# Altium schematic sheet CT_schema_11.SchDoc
size 387 x 385 mm
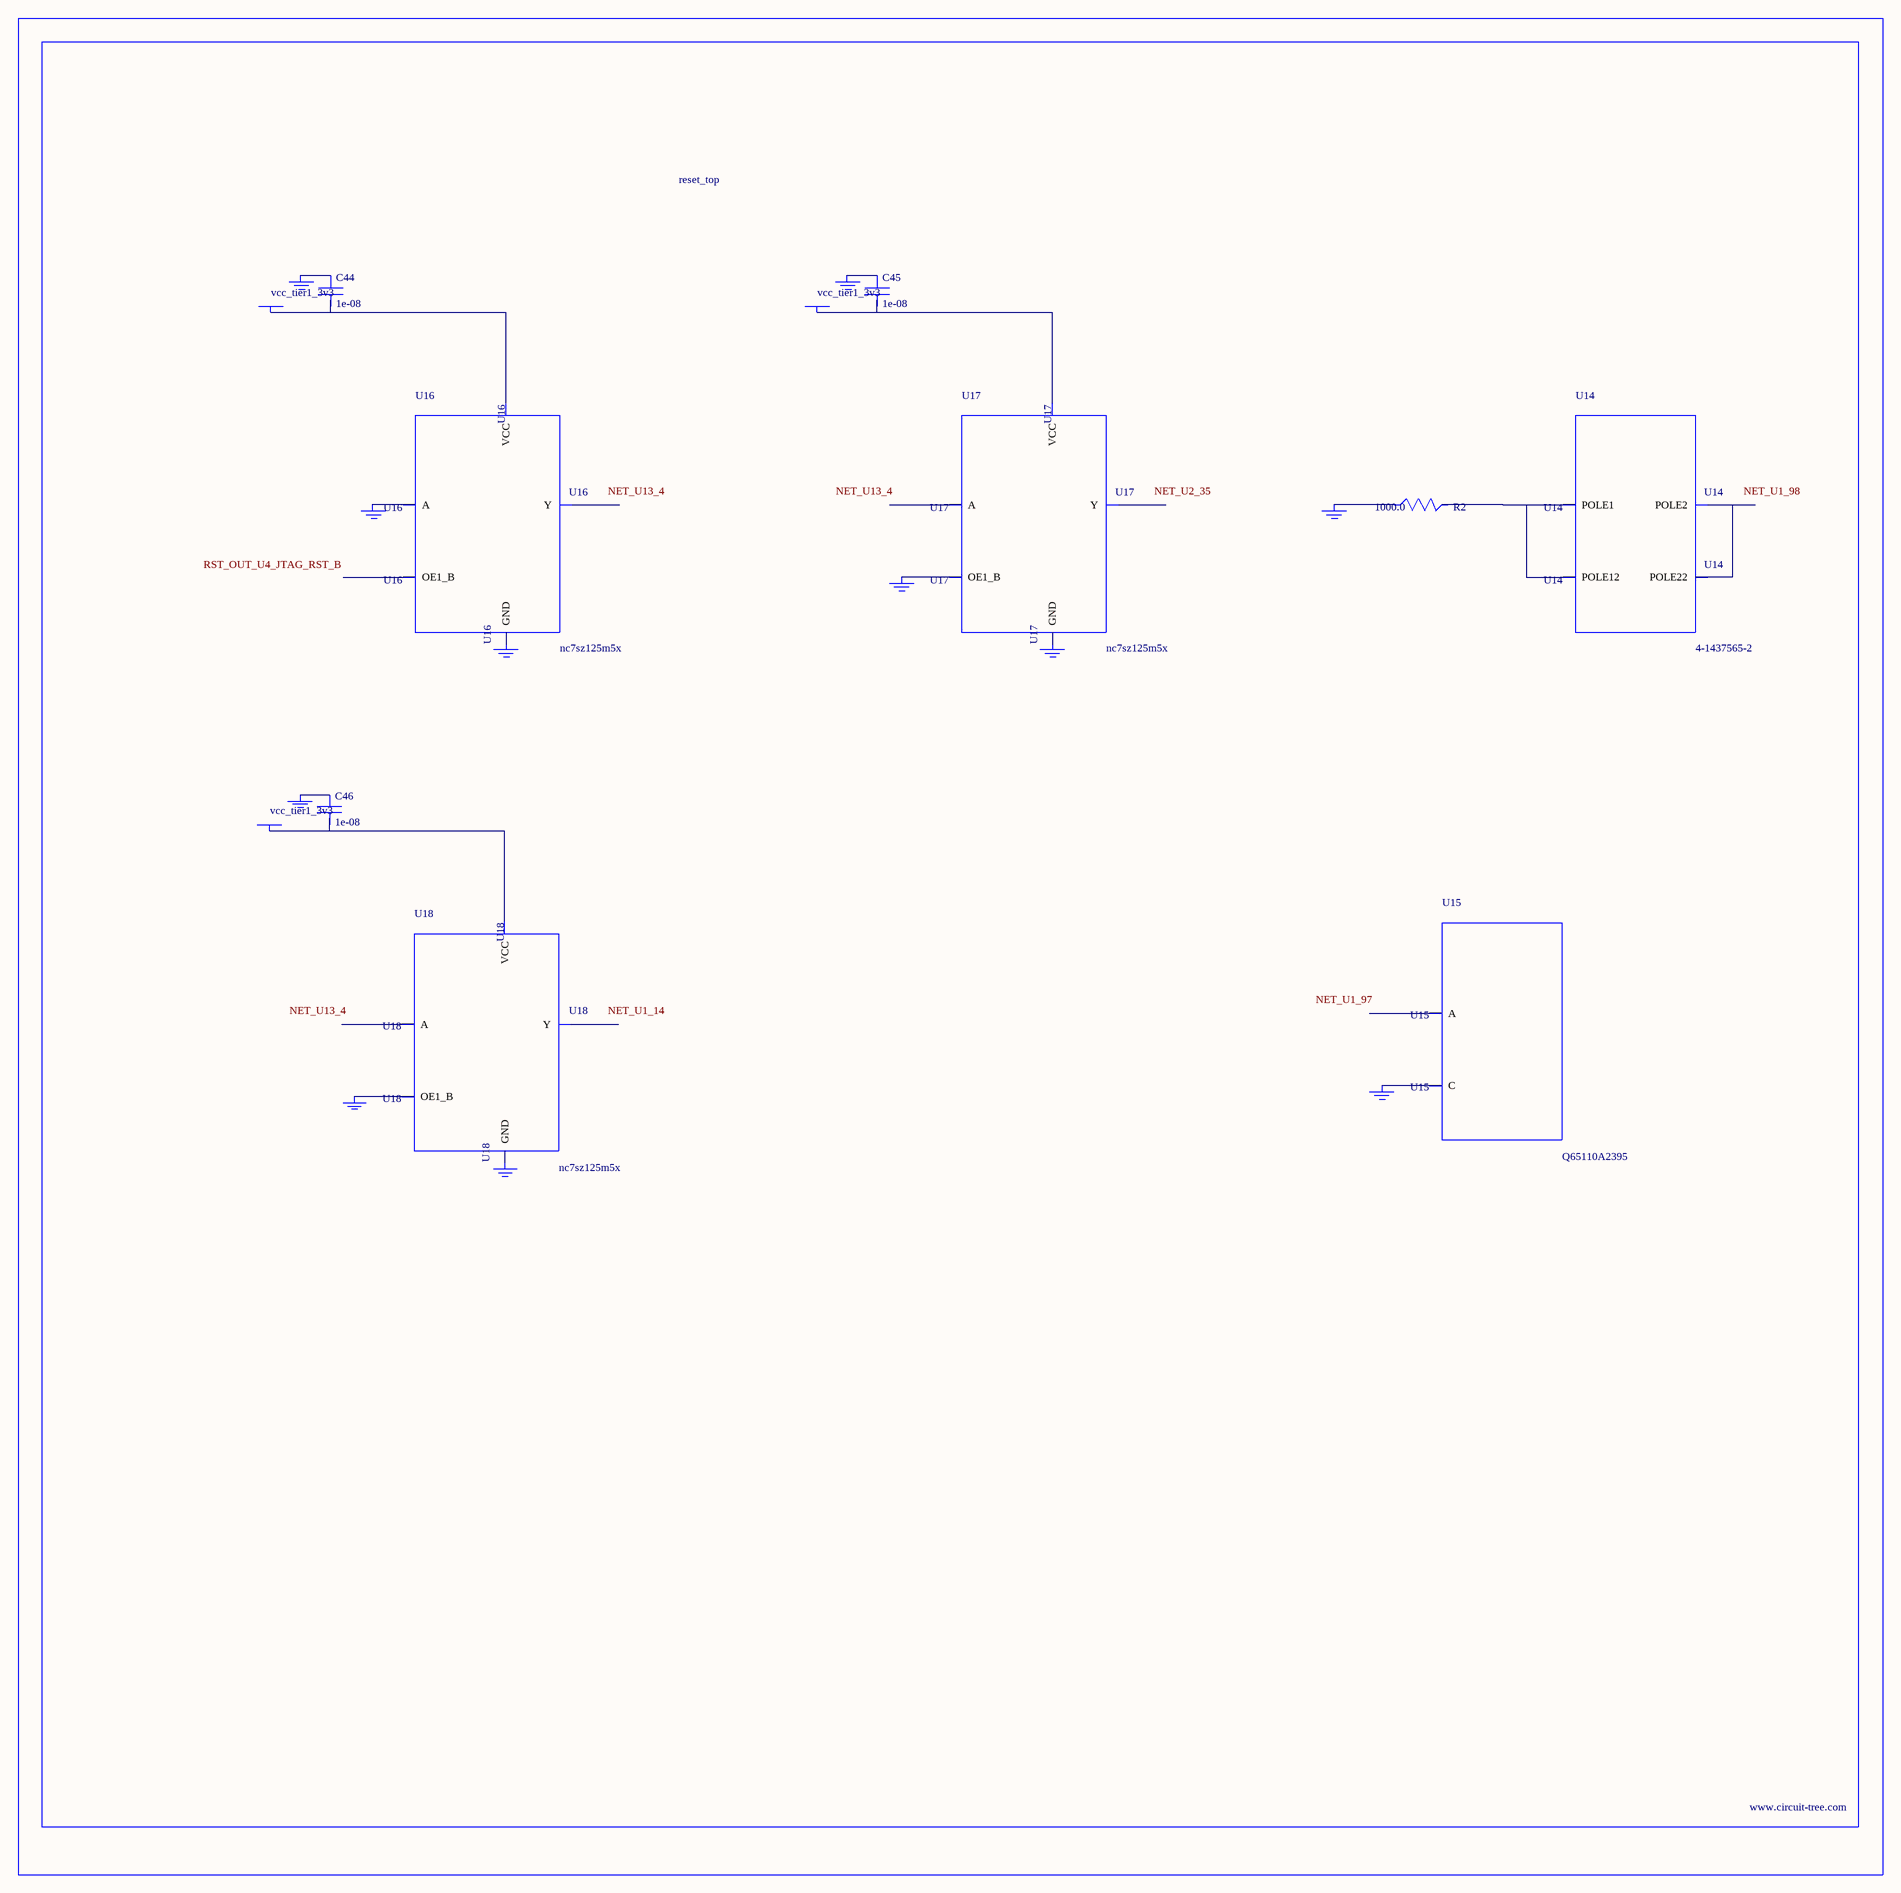
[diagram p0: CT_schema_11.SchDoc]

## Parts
BORDER10  (no value)
C44  1e-08  [C0402]
C45  1e-08  [C0402]
C46  1e-08  [C0402]
GND_INSTANCE_10_0  (no value)
GND_INSTANCE_10_1  (no value)
GND_INSTANCE_10_2  (no value)
GND_INSTANCE_10_3  (no value)
GND_INSTANCE_10_4  (no value)
GND_INSTANCE_10_5  (no value)
GND_INSTANCE_10_6  (no value)
GND_INSTANCE_10_7  (no value)
GND_INSTANCE_10_8  (no value)
GND_INSTANCE_10_9  (no value)
GND_INSTANCE_10_10  (no value)
POWER_INSTANCE_10_0  vcc_tier1_3v3
POWER_INSTANCE_10_1  vcc_tier1_3v3
POWER_INSTANCE_10_2  vcc_tier1_3v3
R2  1000.0  [R0603]
U14  4-1437565-2  [SW_4-1437565-2]
U15  Q65110A2395  [LGM67K-G1J2-24-Z]
U16  nc7sz125m5x  [NC7SZ125M5X]
U17  nc7sz125m5x  [NC7SZ125M5X]
U18  nc7sz125m5x  [NC7SZ125M5X]

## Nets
NetC44_1: C44.1 GND_INSTANCE_10_2.0(GND)
NetC44_2: C44.2 POWER_INSTANCE_10_0.0(PWR) U16.5(VCC)
NetC45_1: C45.1 GND_INSTANCE_10_5.0(GND)
NetC45_2: C45.2 POWER_INSTANCE_10_1.0(PWR) U17.5(VCC)
NetC46_1: C46.1 GND_INSTANCE_10_8.0(GND)
NetC46_2: C46.2 POWER_INSTANCE_10_2.0(PWR) U18.5(VCC)
NetGND_INSTANCE_10_0_0: GND_INSTANCE_10_0.0(GND) R2.1
NetGND_INSTANCE_10_1_0: GND_INSTANCE_10_1.0(GND) U15.C
NetGND_INSTANCE_10_3_0: GND_INSTANCE_10_3.0(GND) U16.2(A)
NetGND_INSTANCE_10_4_0: GND_INSTANCE_10_4.0(GND) U16.3(GND)
NetGND_INSTANCE_10_6_0: GND_INSTANCE_10_6.0(GND) U17.1(OE1_B)
NetGND_INSTANCE_10_7_0: GND_INSTANCE_10_7.0(GND) U17.3(GND)
NetGND_INSTANCE_10_9_0: GND_INSTANCE_10_9.0(GND) U18.1(OE1_B)
NetGND_INSTANCE_10_10_0: GND_INSTANCE_10_10.0(GND) U18.3(GND)
NetR2_2: R2.2 U14.1(POLE1) U14.2(POLE12)
NetU14_3: U14.3(POLE2) U14.4(POLE22)

Not connected (* = marked no-connect by the designer): U15 A; U16 1(OE1_B) 4(Y); U17 2(A) 4(Y); U18 2(A) 4(Y)

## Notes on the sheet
- Labels drawn without touching a wire or pin: NET_U1_14, NET_U1_97, NET_U1_98, NET_U2_35, NET_U13_4, RST_OUT_U4_JTAG_RST_B

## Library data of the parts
BORDER10 = BORDER_PAGE10
C44-C46 = C0402C103K3RAC
GND_INSTANCE_10_0-GND_INSTANCE_10_10 = GND
POWER_INSTANCE_10_0-POWER_INSTANCE_10_2 = PWR
R2 = RC0603JR-071KL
